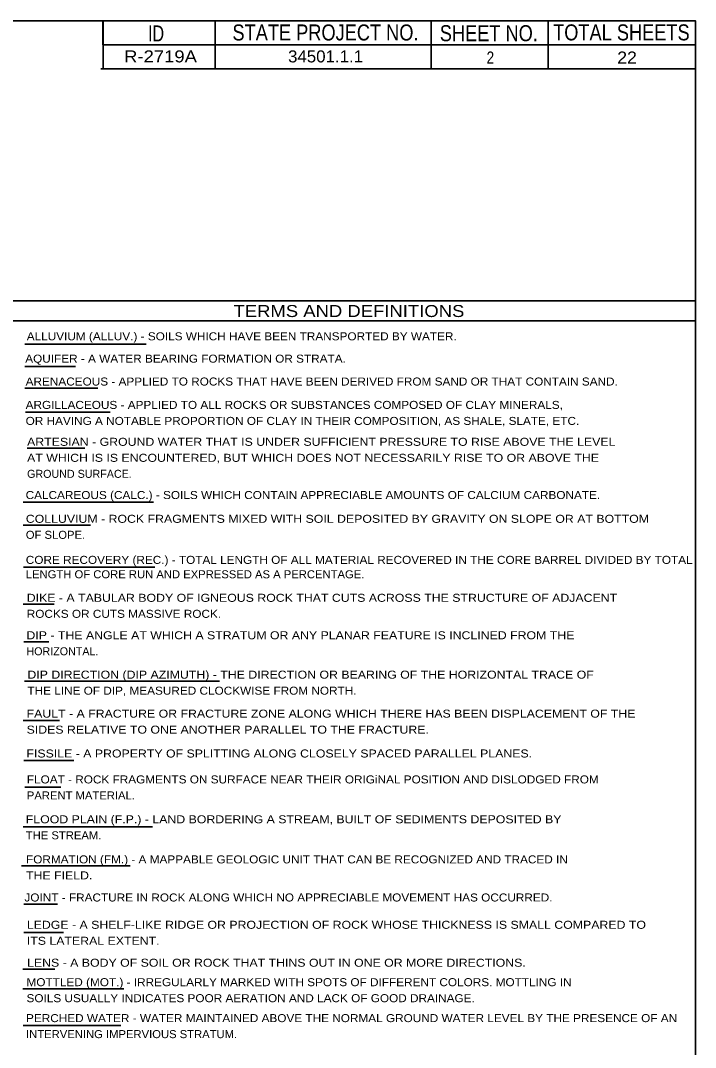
# Model space of a CAD drawing. Extents: x 2137492.6 to 2137529.1, y 2137475.8 to 2137563.
# Drawn here: x 2137519.94 to 2137528.37, y 2137548.89 to 2137561.72 of the extents above; entities that cross this region are included whole.
import ezdxf
from ezdxf.enums import TextEntityAlignment as Align

# ---------------------------------------------------------------- set-up
doc = ezdxf.new("R2010")
doc.units = 0
doc.header["$LTSCALE"] = 0.04
doc.layers.add('1', color=7, linetype='Continuous', lineweight=35)

msp = doc.modelspace()

# ---------------------------------------------------------------- linework, layer by layer
at = {"layer": '1'}
for p, q in [((2137493.171, 2137561.718), (2137528.371, 2137561.718)), ((2137520.971, 2137561.718), (2137520.971, 2137561.418)), ((2137520.972, 2137561.72), (2137520.972, 2137561.12)), ((2137525.071, 2137561.718), (2137525.071, 2137561.118)), ((2137526.533, 2137561.718), (2137526.533, 2137561.118)), ((2137528.371, 2137561.718), (2137528.371, 2137539.727)), ((2137528.371, 2137561.718), (2137528.371, 2137561.118)), ((2137520.971, 2137561.418), (2137528.371, 2137561.418)), ((2137522.371, 2137561.118), (2137520.946, 2137561.118)), ((2137528.371, 2137558.425), (2137528.371, 2137539.727)), ((2137493.171, 2137558.218), (2137528.371, 2137558.218)), ((2137493.171, 2137557.968), (2137528.371, 2137557.968)), ((2137519.993, 2137557.678), (2137521.512, 2137557.678)), ((2137519.993, 2137557.398), (2137520.628, 2137557.398)), ((2137519.993, 2137557.128), (2137520.908, 2137557.128)), ((2137520.005, 2137556.828), (2137521.061, 2137556.828)), ((2137520.023, 2137556.377), (2137520.745, 2137556.377)), ((2137519.974, 2137555.702), (2137521.601, 2137555.702)), ((2137519.973, 2137555.415), (2137520.813, 2137555.415)), ((2137519.978, 2137554.891), (2137521.619, 2137554.891)), ((2137519.973, 2137554.428), (2137520.361, 2137554.428)), ((2137519.983, 2137553.958), (2137520.295, 2137553.958)), ((2137519.992, 2137553.467), (2137522.426, 2137553.467)), ((2137519.974, 2137552.977), (2137520.426, 2137552.977)), ((2137519.983, 2137552.477), (2137520.608, 2137552.477)), ((2137519.993, 2137552.143), (2137520.445, 2137552.143)), ((2137519.972, 2137551.645), (2137521.588, 2137551.645)), ((2137519.953, 2137551.159), (2137519.962, 2137551.159)), ((2137519.962, 2137551.159), (2137521.31, 2137551.159)), ((2137519.983, 2137550.68), (2137520.403, 2137550.68)), ((2137519.982, 2137550.328), (2137520.477, 2137550.328)), ((2137519.971, 2137549.87), (2137520.37, 2137549.87)), ((2137519.97, 2137549.624), (2137521.23, 2137549.624)), ((2137519.974, 2137549.163), (2137521.192, 2137549.163))]:
    msp.add_line(p, q, dxfattribs=at)
msp.add_lwpolyline([(2137522.371, 2137561.718), (2137528.371, 2137561.718), (2137528.371, 2137561.118), (2137522.371, 2137561.118)], close=True, dxfattribs=at)

# ---------------------------------------------------------------- texts
for s, height, width, p in [('ID', 0.2, 0.75, (2137521.634, 2137561.459)), ('STATE PROJECT NO.', 0.2, 0.85, (2137523.75, 2137561.471)), ('SHEET NO.', 0.2, 0.85, (2137525.79, 2137561.462)), ('TOTAL SHEETS', 0.2, 0.85, (2137527.446, 2137561.472)), ('R-2719A', 0.15, 1.15, (2137521.6895, 2137561.197)), ('34501.1.1', 0.15, 1.05, (2137523.751, 2137561.197))]:
    msp.add_text(s, height=height, dxfattribs=dict(at, width=width)).set_placement(p, align=Align.CENTER)
for s, height, width, p in [('2', 0.15, 0.85, (2137525.762, 2137561.183)), ('22', 0.15, 1.1, (2137527.394, 2137561.183)), ('TERMS AND DEFINITIONS', 0.15, 1.15, (2137522.601, 2137558.016)), ('ALLUVIUM (ALLUV.) - SOILS WHICH HAVE BEEN TRANSPORTED BY WATER.', 0.1, 1.1, (2137520.019, 2137557.725)), ('AQUIFER - A WATER BEARING FORMATION OR STRATA.', 0.1, 1.1, (2137520, 2137557.446)), ('ARENACEOUS - APPLIED TO ROCKS THAT HAVE BEEN DERIVED FROM SAND OR THAT CONTAIN SAND.', 0.1, 1.1, (2137520.005, 2137557.16)), ('ARGILLACEOUS - APPLIED TO ALL ROCKS OR SUBSTANCES COMPOSED OF CLAY MINERALS,', 0.1, 1.1, (2137520.005, 2137556.868)), ('OR HAVING A NOTABLE PROPORTION OF CLAY IN THEIR COMPOSITION, AS SHALE, SLATE, ETC.', 0.1, 1.1, (2137520.005, 2137556.668)), ('ARTESIAN - GROUND WATER THAT IS UNDER SUFFICIENT PRESSURE TO RISE ABOVE THE LEVEL ', 0.1, 1.15, (2137520.023, 2137556.407)), ('AT WHICH IS IS ENCOUNTERED, BUT WHICH DOES NOT NECESSARILY RISE TO OR ABOVE THE ', 0.1, 1.15, (2137520.023, 2137556.207)), ('CALCAREOUS (CALC.) - SOILS WHICH CONTAIN APPRECIABLE AMOUNTS OF CALCIUM CARBONATE.', 0.1, 1.1, (2137520.005, 2137555.742)), ('COLLUVIUM - ROCK FRAGMENTS MIXED WITH SOIL DEPOSITED BY GRAVITY ON SLOPE OR AT BOTTOM ', 0.1, 1.15, (2137520.007, 2137555.445)), ('OF SLOPE.', 0.1, 1.05, (2137520.007, 2137555.245)), ('CORE RECOVERY (REC.) - TOTAL LENGTH OF ALL MATERIAL RECOVERED IN THE CORE BARREL DIVIDED BY TOTAL', 0.1, 1.1, (2137520.007, 2137554.932)), ('LENGTH OF CORE RUN AND EXPRESSED AS A PERCENTAGE.', 0.1, 1.05, (2137520.007, 2137554.752)), ('DIKE - A TABULAR BODY OF IGNEOUS ROCK THAT CUTS ACROSS THE STRUCTURE OF ADJACENT', 0.1, 1.15, (2137520.019, 2137554.458)), ('ROCKS OR CUTS MASSIVE ROCK.', 0.1, 1.1, (2137520.019, 2137554.258)), ('DIP - THE ANGLE AT WHICH A STRATUM OR ANY PLANAR FEATURE IS INCLINED FROM THE', 0.1, 1.15, (2137520.015, 2137553.99)), ('DIP DIRECTION (DIP AZIMUTH) - THE DIRECTION OR BEARING OF THE HORIZONTAL TRACE OF ', 0.1, 1.15, (2137520.027, 2137553.498)), ('THE LINE OF DIP, MEASURED CLOCKWISE FROM NORTH.', 0.1, 1.1, (2137520.027, 2137553.298)), ('FAULT - A FRACTURE OR FRACTURE ZONE ALONG WHICH THERE HAS BEEN DISPLACEMENT OF THE', 0.1, 1.15, (2137520.017, 2137553.011)), ('SIDES RELATIVE TO ONE ANOTHER PARALLEL TO THE FRACTURE.', 0.1, 1.15, (2137520.017, 2137552.811)), ('FISSILE - A PROPERTY OF SPLITTING ALONG CLOSELY SPACED PARALLEL PLANES.', 0.1, 1.15, (2137520.015, 2137552.513)), ('FLOAT - ROCK FRAGMENTS ON SURFACE NEAR THEIR ORIGiNAL POSITION AND DISLODGED FROM ', 0.1, 1.1, (2137520.02, 2137552.189)), ('PARENT MATERIAL.', 0.1, 1.05, (2137520.02, 2137551.989)), ('FLOOD PLAIN (F.P.) - LAND BORDERING A STREAM, BUILT OF SEDIMENTS DEPOSITED BY', 0.1, 1.15, (2137520.007, 2137551.691)), ('THE STREAM.', 0.1, 1.05, (2137520.007, 2137551.491)), ('FORMATION (FM.) - A MAPPABLE GEOLOGIC UNIT THAT CAN BE RECOGNIZED AND TRACED IN', 0.1, 1.1, (2137520.01, 2137551.19)), ('THE FIELD.', 0.1, 1.15, (2137520.01, 2137550.99)), ('JOINT - FRACTURE IN ROCK ALONG WHICH NO APPRECIABLE MOVEMENT HAS OCCURRED.', 0.1, 1.1, (2137519.99, 2137550.714)), ('LEDGE - A SHELF-LIKE RIDGE OR PROJECTION OF ROCK WHOSE THICKNESS IS SMALL COMPARED TO ', 0.1, 1.15, (2137520.02, 2137550.373)), ('ITS LATERAL EXTENT.', 0.1, 1.15, (2137520.02, 2137550.173)), ('LENS - A BODY OF SOIL OR ROCK THAT THINS OUT IN ONE OR MORE DIRECTIONS.', 0.1, 1.15, (2137520.023, 2137549.899)), ('MOTTLED (MOT.) - IRREGULARLY MARKED WITH SPOTS OF DIFFERENT COLORS. MOTTLING IN ', 0.1, 1.1, (2137520.016, 2137549.656)), ('SOILS USUALLY INDICATES POOR AERATION AND LACK OF GOOD DRAINAGE.', 0.1, 1.1, (2137520.016, 2137549.456)), ('PERCHED WATER - WATER MAINTAINED ABOVE THE NORMAL GROUND WATER LEVEL BY THE PRESENCE OF AN ', 0.1, 1.1, (2137520.01, 2137549.207)), ('INTERVENING IMPERVIOUS STRATUM.', 0.1, 1.05, (2137520.01, 2137549.007))]:
    msp.add_text(s, height=height, dxfattribs=dict(at, width=width)).set_placement(p)
for s, p in [('GROUND SURFACE.', (2137520.023, 2137556.007)), ('HORIZONTAL.', (2137520.015, 2137553.79))]:
    msp.add_text(s, height=0.1, dxfattribs=at).set_placement(p)

doc.saveas('drawing.dxf')
